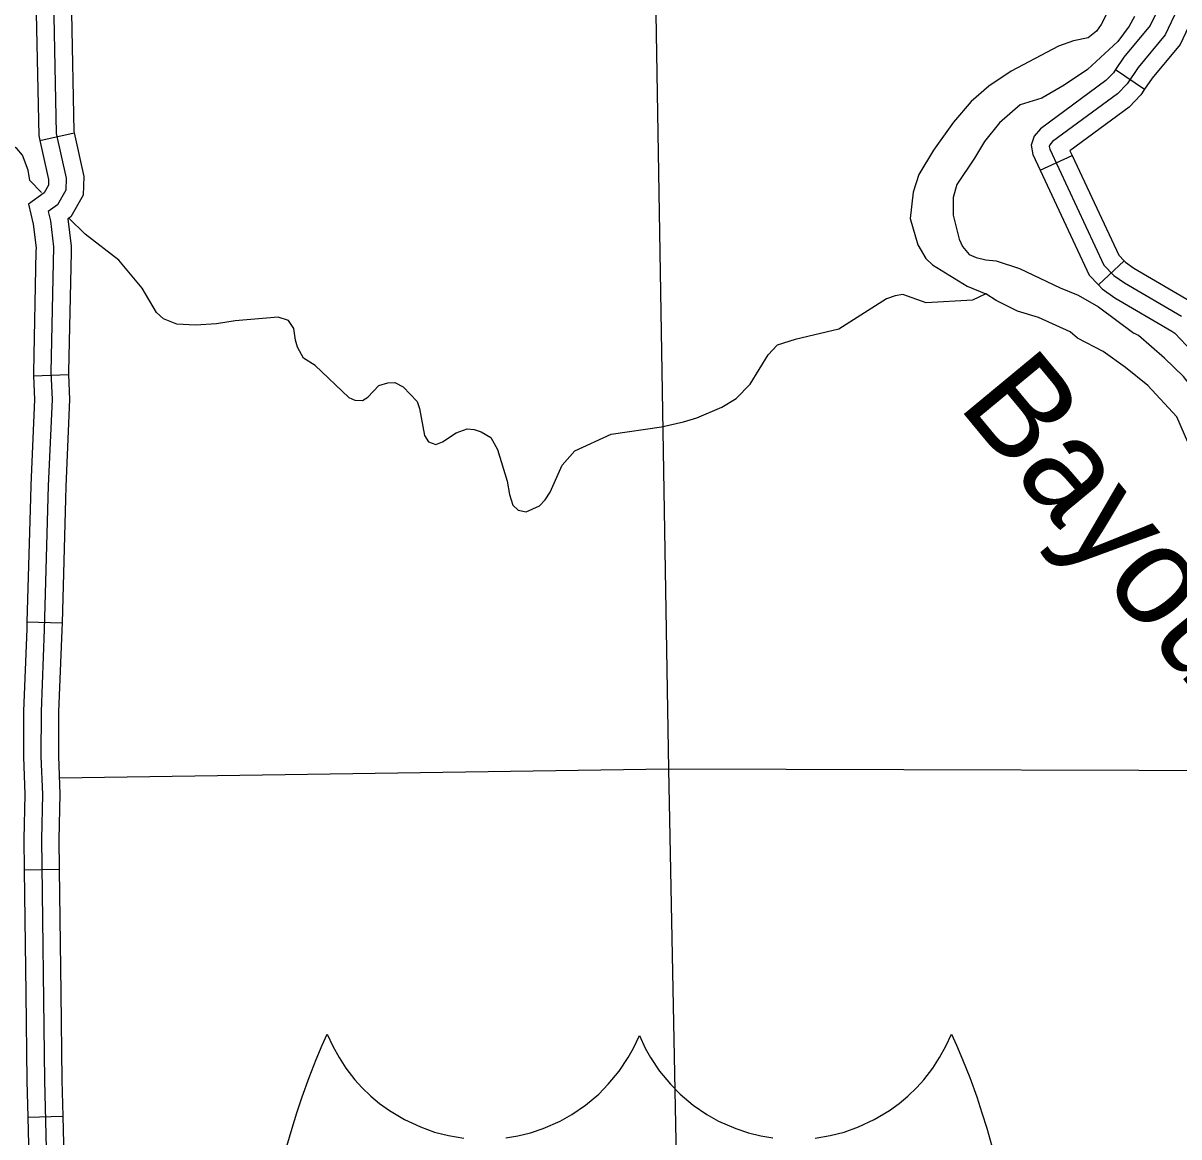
# Model space of a CAD drawing. Extents: x 1084508 to 1142749, y 1057638 to 1093403.
# Drawn here: x 1088582 to 1090132, y 1071566 to 1073059 of the extents above; entities that cross this region are included whole.
import ezdxf

# ---------------------------------------------------------------- set-up
doc = ezdxf.new("R2010")
doc.units = 0
for name, color, linetype in [('Level 23', 7, 'Continuous'), ('Level 32', 7, 'Continuous'), ('Level 35', 7, 'Continuous'), ('Level 45', 7, 'Continuous'), ('Level 5', 7, 'Continuous'), ('Level 7', 7, 'Continuous')]:
    doc.layers.add(name, color=color, linetype=linetype)

msp = doc.modelspace()

# ---------------------------------------------------------------- linework, layer by layer
at = {"layer": 'Level 23'}
for points in [[(1088936.1, 1071553.1), (1088943, 1071577.6), (1088949.3, 1071598.1), (1088956.4, 1071619.3), (1088965.8, 1071645.2), (1088975.5, 1071669.6), (1088983.6, 1071688.5), (1088990.3, 1071703.4), (1088997.6, 1071687.4), (1089006.1, 1071672), (1089015.3, 1071657.9), (1089027.3, 1071642.4), (1089036.8, 1071631.9), (1089048.6, 1071620.5), (1089060.5, 1071610.5), (1089073.5, 1071601.1), (1089094, 1071588.8), (1089115.1, 1071579), (1089134.1, 1071572.2), (1089153, 1071567.4), (1089173.2, 1071564)], [(1089229.9, 1071564.4), (1089245.7, 1071567.1), (1089262.6, 1071571.3), (1089279.6, 1071576.9), (1089302.5, 1071587), (1089318.3, 1071595.9), (1089336.7, 1071608.4), (1089354.3, 1071623.2), (1089367.1, 1071636.2), (1089381.8, 1071654), (1089393.9, 1071672.1), (1089401, 1071684.8), (1089408.8, 1071701.6)], [(1089408.8, 1071701.6), (1089416.6, 1071684.8), (1089423.7, 1071672.1), (1089435.8, 1071654), (1089450.5, 1071636.2), (1089463.3, 1071623.2), (1089480.9, 1071608.4), (1089499.3, 1071595.9), (1089515.1, 1071587), (1089538, 1071576.9), (1089555, 1071571.3), (1089571.9, 1071567.1), (1089587.7, 1071564.4)], [(1089644.4, 1071564), (1089664.6, 1071567.4), (1089683.4, 1071572.2), (1089702.5, 1071579), (1089723.6, 1071588.8), (1089744.1, 1071601.1), (1089757.1, 1071610.5), (1089768.9, 1071620.5), (1089780.7, 1071631.9), (1089790.2, 1071642.4), (1089802.3, 1071657.9), (1089811.5, 1071672), (1089820, 1071687.4), (1089827.3, 1071703.4), (1089834, 1071688.5), (1089842.1, 1071669.6), (1089851.8, 1071645.2), (1089861.2, 1071619.3), (1089868.3, 1071598.1), (1089874.6, 1071577.6), (1089881.5, 1071553.1)]]:
    msp.add_lwpolyline(points, dxfattribs=at)
at = {"layer": 'Level 32'}
for p, q in [((1090047.4, 1072996.6), (1090086.4, 1072970.3)), ((1089946.4, 1072861.6), (1089989.1, 1072881.6)), ((1090024.7, 1072707.9), (1090058.9, 1072740.2))]:
    msp.add_line(p, q, dxfattribs=at)
for points in [[(1090156.6, 1073133.5), (1090159.5, 1073121.6), (1090160.4, 1073098.9), (1090152.9, 1073069.9), (1090134, 1073030.3), (1090096.4, 1072985.1), (1090086.4, 1072970.3)], [(1090110.8, 1073122.3), (1090112.6, 1073115), (1090113.1, 1073103.9), (1090108.5, 1073086.1), (1090094, 1073055.9), (1090058.7, 1073013.4), (1090047.4, 1072996.6)], [(1090130.7, 1073078), (1090114, 1073043.1), (1090077.6, 1072999.3), (1090062.9, 1072977.5), (1090050.2, 1072964.1), (1089963, 1072900), (1089959.3, 1072895.6), (1089958.6, 1072893.5), (1089959.2, 1072889.9), (1090031.9, 1072734.5), (1090045.1, 1072720.5), (1090059.2, 1072710.5), (1090135.7, 1072665.8)], [(1090047.4, 1072996.6), (1090044.5, 1072992.3), (1090034.6, 1072981.8), (1089946.7, 1072917.3), (1089938.3, 1072907.2), (1089934.4, 1072895.3), (1089936.5, 1072882.8), (1089946.4, 1072861.6)], [(1090086.4, 1072970.3), (1090081.4, 1072962.8), (1090065.8, 1072946.4), (1089986.1, 1072887.8), (1089989.1, 1072881.6)], [(1089989.1, 1072881.6), (1090051.6, 1072747.9), (1090058.9, 1072740.2)], [(1089946.4, 1072861.6), (1090012.2, 1072721.1), (1090024.7, 1072707.9)], [(1090058.9, 1072740.2), (1090060.6, 1072738.4), (1090072, 1072730.4), (1090148.4, 1072685.7), (1090157.8, 1072679.2), (1090191.7, 1072643.4)], [(1090024.7, 1072707.9), (1090029.6, 1072702.6), (1090046.5, 1072690.7), (1090123.1, 1072646), (1090127, 1072643.3), (1090157.5, 1072611)]]:
    msp.add_lwpolyline(points, dxfattribs=at)
at = {"layer": 'Level 35'}
for points in [[(1090041.6, 1073083), (1090028.2, 1073057.2), (1090022, 1073048.1), (1090010.8, 1073039.1), (1089991.1, 1073035.2), (1089970.7, 1073028), (1089907.3, 1072994.4), (1089877.3, 1072974.3), (1089854, 1072953.8), (1089829.9, 1072926.3), (1089803.2, 1072888.6), (1089783.5, 1072855.9), (1089776, 1072832.3), (1089771.8, 1072797.1), (1089782.1, 1072761.6), (1089793, 1072743.5), (1089801.8, 1072735), (1089848.6, 1072706.4), (1089873.3, 1072695.8)], [(1090072.8, 1073067.6), (1090065.8, 1073055), (1090050.6, 1073034.2), (1090009.7, 1072996.8), (1089978.5, 1072975.7), (1089948.7, 1072958.4), (1089919.6, 1072949.3), (1089891.6, 1072925.4), (1089871.6, 1072900), (1089858.4, 1072877.7), (1089834.7, 1072842.3), (1089829.8, 1072825.1), (1089829.5, 1072801.4), (1089837.8, 1072769.3), (1089842, 1072759.4), (1089851.2, 1072748.7), (1089860.5, 1072744.7), (1089873.3, 1072741.5), (1089887.1, 1072740.2), (1089918.4, 1072730.1)], [(1088607.1, 1072831.8), (1088591.2, 1072847.8), (1088589, 1072861.9), (1088581.3, 1072881.8), (1088574, 1072890.9), (1088564, 1072896.5), (1088543, 1072895.6), (1088528, 1072892.8), (1088504.8, 1072881.2)], [(1088973.8, 1072599.9), (1088958.5, 1072609.8), (1088950.4, 1072624.3), (1088947.8, 1072633.7), (1088945.2, 1072649.6), (1088938.2, 1072660.1), (1088924.5, 1072664.5), (1088866.5, 1072659.6), (1088841.8, 1072655.7), (1088813.6, 1072653.9), (1088788.7, 1072655.1), (1088770.8, 1072662.5), (1088761, 1072670.9), (1088742, 1072703.5), (1088710.9, 1072741), (1088665.5, 1072775.8), (1088643.8, 1072797.5)], [(1089918.4, 1072730.1), (1089973, 1072704), (1089997.3, 1072694.3), (1090024.4, 1072678.5), (1090072, 1072643.4)], [(1089873.3, 1072695.8), (1089855.4, 1072687.5), (1089793.3, 1072683.9), (1089762.3, 1072694.9), (1089751.7, 1072693.2), (1089740.2, 1072689.2), (1089676.2, 1072648.7), (1089617.6, 1072634.9), (1089593.7, 1072627.1)], [(1089986.7, 1072645.1), (1089944.1, 1072664.1), (1089915.8, 1072672.6), (1089887.5, 1072687.2), (1089873.3, 1072695.8)], [(1090354.4, 1072222.6), (1090333, 1072232.9), (1090297.5, 1072255.3), (1090246.8, 1072303.6), (1090235.1, 1072317.4), (1090226.8, 1072329.7), (1090216.7, 1072351.1), (1090203.5, 1072391.8), (1090186, 1072421.4), (1090165, 1072449.7), (1090129.5, 1072531.2), (1090090.8, 1072573), (1090060.9, 1072597.2), (1090030.8, 1072618.8), (1089996.4, 1072636.6), (1089986.7, 1072645.1)], [(1090206.5, 1072456.7), (1090179.7, 1072509.6), (1090151.5, 1072568.7), (1090138.4, 1072585.2), (1090112.9, 1072609.6), (1090078.3, 1072640.2), (1090072, 1072643.4)], [(1088973.8, 1072599.9), (1089019, 1072556.8), (1089027, 1072553.2), (1089037.3, 1072552.9), (1089044.7, 1072557.6), (1089059.5, 1072573.2), (1089071.3, 1072576.7), (1089080.7, 1072577), (1089092.2, 1072571.4), (1089110.7, 1072551.6), (1089113.8, 1072542.2), (1089120.6, 1072506), (1089126.2, 1072497.7), (1089136, 1072493.9), (1089145, 1072497.4), (1089163.1, 1072509.6), (1089177.7, 1072514.8), (1089187.1, 1072514.2), (1089196.6, 1072511), (1089209.4, 1072503.2), (1089218.7, 1072487.2), (1089231.6, 1072444.9), (1089234.7, 1072426.7), (1089239.2, 1072412.7), (1089246.3, 1072406), (1089257.1, 1072403.6), (1089275, 1072411.7), (1089282.6, 1072419.8), (1089289.1, 1072430.1), (1089305.2, 1072466.1), (1089322.4, 1072485.6), (1089370.9, 1072507.6), (1089438.3, 1072517.7), (1089468.2, 1072524.3), (1089485.9, 1072529.9), (1089519.6, 1072544.2), (1089538.6, 1072555.5), (1089557.4, 1072574.7), (1089581.5, 1072614.2), (1089593.7, 1072627.1)]]:
    msp.add_lwpolyline(points, dxfattribs=at)
at = {"layer": 'Level 45'}
for p, q in [((1088604.6, 1072901.5), (1088650.6, 1072911.9)), ((1088596.3, 1072585.8), (1088643.3, 1072587.6)), ((1088587.4, 1072256.1), (1088634.5, 1072254.8)), ((1088583.8, 1071923.8), (1088630.9, 1071924.4)), ((1088588.5, 1071592.1), (1088635.6, 1071593.3))]:
    msp.add_line(p, q, dxfattribs=at)
for points in [[(1088582.8, 1075226.2), (1088606.9, 1074130.2), (1088623.7, 1073716.9), (1088621.9, 1073158.1), (1088626.7, 1072910.8), (1088640.2, 1072851.2), (1088639.6, 1072834.8), (1088628.5, 1072815.4), (1088616, 1072806.4), (1088619, 1072793.6), (1088623.3, 1072758.8), (1088619.6, 1072591)], [(1088600, 1073071.9), (1088603.2, 1072908), (1088604.6, 1072901.5)], [(1088647.1, 1073072.8), (1088650.2, 1072913.7), (1088650.6, 1072911.9)], [(1088650.6, 1072911.9), (1088663.8, 1072853.4), (1088662.9, 1072828.1), (1088646.4, 1072799.3), (1088642.4, 1072796.4), (1088646.9, 1072760), (1088646.7, 1072751.9)], [(1088604.6, 1072901.5), (1088616.5, 1072849), (1088616.3, 1072841.4), (1088610.6, 1072831.5), (1088589.4, 1072816.2), (1088595.8, 1072789.4), (1088599.7, 1072757.6), (1088599.6, 1072752.9)], [(1088599.6, 1072752.9), (1088596.1, 1072590.8), (1088596.3, 1072585.8)], [(1088646.7, 1072751.9), (1088643.2, 1072591.2), (1088643.3, 1072587.6)], [(1088596.3, 1072585.8), (1088597.5, 1072554.3), (1088592.6, 1072439.5), (1088592.1, 1072421.8)], [(1088619.6, 1072591), (1088621.1, 1072554.3), (1088616.1, 1072438.7), (1088610.7, 1072246), (1088606.5, 1072136.1), (1088606.3, 1072075.7), (1088608.3, 1072024.8), (1088606.8, 1071964.7), (1088610.9, 1071641.3), (1088642.6, 1070349.8)], [(1088643.3, 1072587.6), (1088644.6, 1072554.2), (1088639.7, 1072437.8), (1088639.2, 1072420.5)], [(1088592.1, 1072421.8), (1088587.4, 1072256.1)], [(1088639.2, 1072420.5), (1088634.5, 1072254.8)], [(1088587.4, 1072256.1), (1088587.2, 1072246.8), (1088583, 1072136.6), (1088582.8, 1072089.9)], [(1088634.5, 1072254.8), (1088634.2, 1072245.2), (1088630, 1072135.6), (1088629.9, 1072089.7)], [(1088582.8, 1072089.9), (1088582.8, 1072075.3), (1088584.7, 1072024.7), (1088583.3, 1071964.9), (1088583.8, 1071923.8)], [(1088629.9, 1072089.7), (1088629.9, 1072076.1), (1088631.8, 1072025), (1088630.4, 1071964.6), (1088630.9, 1071924.4)], [(1088583.8, 1071923.8), (1088585.9, 1071758.1)], [(1088630.9, 1071924.4), (1088633, 1071758.7)], [(1088585.9, 1071758.1), (1088587.3, 1071640.9), (1088588.5, 1071592.1)], [(1088633, 1071758.7), (1088634.4, 1071641.7), (1088635.6, 1071593.3)], [(1088588.5, 1071592.1), (1088592.6, 1071426.5)], [(1088635.6, 1071593.3), (1088639.7, 1071427.6)]]:
    msp.add_lwpolyline(points, dxfattribs=at)
at = {"layer": 'Level 5'}
msp.add_lwpolyline([(1090394.4, 1072056.1), (1089447.7, 1072058.6), (1088631, 1072046.8)], dxfattribs=at)
at = {"layer": 'Level 7'}
for points in [[(1089429.2, 1073178.5), (1089447.7, 1072058.6)], [(1089447.7, 1072058.6), (1089464, 1071242.7)]]:
    msp.add_lwpolyline(points, dxfattribs=at)

# ---------------------------------------------------------------- texts
at = {"layer": 'Level 35'}
msp.add_text('Bayou', height=132.58, rotation=309.6109, dxfattribs=at).set_placement((1089834.6, 1072546))

doc.saveas('drawing.dxf')
